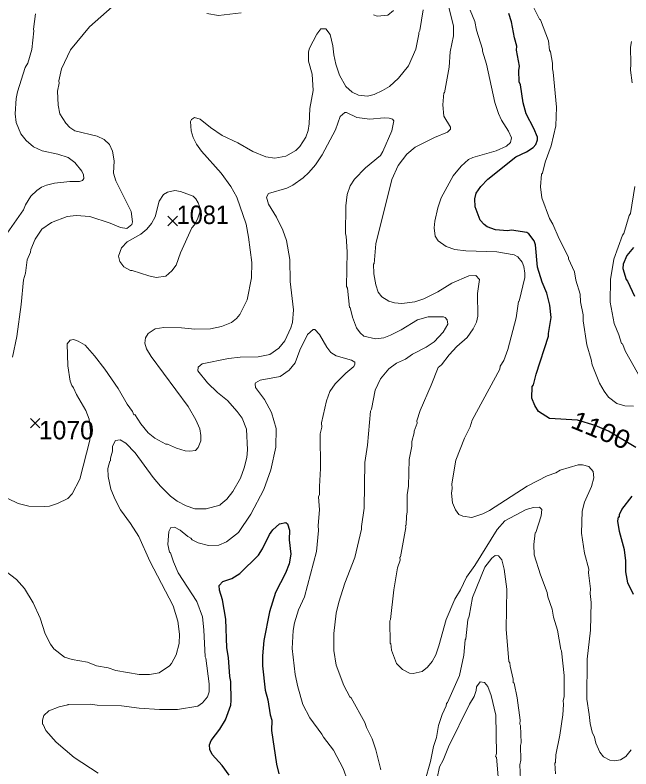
# Model space of a CAD drawing. Extents: x 265.7 to 292.1, y 7676.2 to 7704.2.
# Drawn here: x 285.928 to 288.593, y 7698.298 to 7701.561 of the extents above; entities that cross this region are included whole.
import ezdxf
from ezdxf.enums import TextEntityAlignment as Align

# ---------------------------------------------------------------- set-up
doc = ezdxf.new("R2010")
doc.units = 0
doc.header["$LTSCALE"] = 0.032
for name, color, linetype, lineweight in [('1', 7, 'Continuous', 25), ('2', 7, 'Continuous', 13), ('21', 7, 'Continuous', 25)]:
    doc.layers.add(name, color=color, linetype=linetype, lineweight=lineweight)
doc.layers.add('61', color=7, linetype='Continuous')

msp = doc.modelspace()

# ---------------------------------------------------------------- linework, layer by layer
at = {"layer": '1'}
for points in [[(288.6148, 7699.6898), (288.4962, 7699.76), (288.4378, 7699.7845), (288.3624, 7699.8071), (288.2413, 7699.8143), (288.1934, 7699.8446), (288.1767, 7699.871), (288.1639, 7699.9029), (288.1663, 7699.9539), (288.1711, 7699.9603), (288.1831, 7700.0066), (288.2365, 7700.1718), (288.2357, 7700.1822), (288.2477, 7700.2524), (288.2429, 7700.3051), (288.2294, 7700.3577), (288.2086, 7700.4056), (288.1887, 7700.4694), (288.1799, 7700.5668), (288.1751, 7700.5843), (288.152, 7700.6147), (288.1432, 7700.6202), (288.077, 7700.6306), (288.0594, 7700.6274), (288.0067, 7700.6314), (287.9716, 7700.645), (287.9573, 7700.6553), (287.9405, 7700.6737), (287.919, 7700.7312), (287.9174, 7700.7663), (287.9237, 7700.7902), (287.9437, 7700.8189), (287.9732, 7700.8508), (288.0945, 7700.9482), (288.1408, 7700.9689), (288.1703, 7700.9873), (288.1823, 7701.0009), (288.1887, 7701.0216), (288.1887, 7701.0328), (288.1735, 7701.0695), (288.14, 7701.1333), (288.1272, 7701.1812), (288.1153, 7701.2586), (288.1097, 7701.2722), (288.1081, 7701.3217), (288.1105, 7701.3392), (288.0985, 7701.4094), (288.0993, 7701.427), (288.0889, 7701.4621), (288.0761, 7701.5323), (288.0642, 7701.5674)], [(288.6044, 7700.5556), (288.5757, 7700.5205), (288.5589, 7700.4822), (288.5581, 7700.4646), (288.5725, 7700.416), (288.5789, 7700.4088), (288.6084, 7700.3441)], [(288.6044, 7699.0538), (288.5797, 7699.1033), (288.5717, 7699.1512), (288.5717, 7699.1991), (288.5653, 7699.247), (288.543, 7699.3252), (288.5366, 7699.3709), (288.5388, 7699.3896), (288.543, 7699.3898), (288.543, 7699.3994), (288.5533, 7699.4209), (288.598, 7699.4792)], [(286.8545, 7698.2718), (286.8241, 7698.3133), (286.7811, 7698.3612), (286.7707, 7698.382), (286.7691, 7698.4027), (286.7771, 7698.4211), (286.8146, 7698.4697), (286.8385, 7698.5112), (286.8609, 7698.5735), (286.8632, 7698.5942), (286.8617, 7698.6772), (286.8577, 7698.698), (286.8521, 7698.7809), (286.8449, 7698.8224), (286.8393, 7698.9469), (286.8249, 7699.0299), (286.8122, 7699.0714), (286.8106, 7699.0921), (286.8266, 7699.1097), (286.8657, 7699.1225), (286.9008, 7699.144), (286.9813, 7699.223), (286.9989, 7699.2501), (287.0284, 7699.3124), (287.0436, 7699.3331), (287.0723, 7699.3587), (287.1003, 7699.365), (287.1066, 7699.3594), (287.1154, 7699.3315), (287.1138, 7699.29), (287.1218, 7699.2278), (287.1138, 7699.1863), (287.0978, 7699.1448), (287.0548, 7699.0618), (287.0284, 7698.9788), (287.0045, 7698.8544), (286.9989, 7698.7873), (286.9989, 7698.7442), (287.0101, 7698.6389), (287.022, 7698.5974), (287.0324, 7698.532), (287.0396, 7698.5096), (287.038, 7698.465), (287.0587, 7698.3181), (287.0699, 7698.2766)]]:
    msp.add_lwpolyline(points, dxfattribs=at)
at = {"layer": '2'}
for points in [[(285.9169, 7700.08), (285.9352, 7700.1694), (285.9536, 7700.3082), (285.964, 7700.4152), (285.9727, 7700.4439), (285.9799, 7700.5013), (285.9943, 7700.5349), (285.9959, 7700.546), (286.015, 7700.5907), (286.0437, 7700.6346), (286.0852, 7700.6633), (286.1539, 7700.6897), (286.1922, 7700.6937), (286.2512, 7700.6897), (286.339, 7700.6609), (286.3837, 7700.641), (286.4116, 7700.637), (286.4332, 7700.6553), (286.4363, 7700.6657), (286.4308, 7700.7104), (286.3637, 7700.8429), (286.3542, 7700.8764), (286.3565, 7700.9307), (286.3494, 7700.9721), (286.3358, 7701.0009), (286.3135, 7701.0224), (286.2831, 7701.0376), (286.1858, 7701.0607), (286.165, 7701.0751), (286.1475, 7701.0934), (286.1219, 7701.1333), (286.114, 7701.1716), (286.1116, 7701.2323), (286.118, 7701.2658), (286.1172, 7701.277), (286.1283, 7701.3288), (286.1674, 7701.411), (286.2496, 7701.5108), (286.3486, 7701.5969)], [(287.8312, 7699.0331), (287.7929, 7698.9453), (287.7618, 7698.8304), (287.7482, 7698.7921), (287.733, 7698.7634), (287.7123, 7698.7386), (287.6899, 7698.7203), (287.6508, 7698.7107), (287.6349, 7698.7123), (287.6046, 7698.7283), (287.5782, 7698.7538), (287.5567, 7698.8129), (287.5543, 7698.8408), (287.5511, 7698.8416), (287.5495, 7698.9389), (287.5527, 7698.9445), (287.5671, 7699.073), (287.583, 7699.1688), (287.5942, 7699.2023), (287.5934, 7699.215), (287.5966, 7699.2166), (287.6189, 7699.3435), (287.6173, 7699.3515), (287.6197, 7699.3531), (287.6213, 7699.3922), (287.6253, 7699.4113), (287.6253, 7699.4847), (287.6301, 7699.5215), (287.6341, 7699.638), (287.6453, 7699.6954), (287.6453, 7699.7154), (287.6556, 7699.7529), (287.6548, 7699.7608), (287.6684, 7699.7951), (287.6668, 7699.8047), (287.6804, 7699.8502), (287.729, 7699.9587), (287.7594, 7700.0353), (287.7729, 7700.0473), (287.8064, 7700.0904), (287.84, 7700.1263), (287.8839, 7700.1654), (287.911, 7700.2029), (287.9253, 7700.2316), (287.9309, 7700.2572), (287.9285, 7700.3561), (287.9381, 7700.4168), (287.9221, 7700.4335), (287.8918, 7700.4319), (287.8184, 7700.4008), (287.7578, 7700.3625), (287.6971, 7700.3322), (287.6572, 7700.3202), (287.6014, 7700.313), (287.5695, 7700.3162), (287.5455, 7700.3226), (287.5144, 7700.341), (287.4992, 7700.3617), (287.4889, 7700.3928), (287.4809, 7700.4407), (287.4793, 7700.4846), (287.4817, 7700.4846), (287.4889, 7700.5716), (287.5583, 7700.8493), (287.5862, 7700.9099), (287.6237, 7700.9594), (287.6596, 7700.9889), (287.7434, 7701.0312), (287.7993, 7701.0543), (287.812, 7701.0671), (287.812, 7701.0759), (287.7841, 7701.1238), (287.7793, 7701.1732), (287.7841, 7701.2243), (287.7865, 7701.2251), (287.8064, 7701.336), (287.8104, 7701.4014), (287.8248, 7701.4717), (287.8248, 7701.514), (287.8009, 7701.6105)], [(286.0158, 7701.5658), (286.007, 7701.5004), (286.0086, 7701.4924), (286.0007, 7701.4126), (285.9831, 7701.3536), (285.9719, 7701.3344), (285.9384, 7701.2291), (285.9328, 7701.2004), (285.928, 7701.1333), (285.932, 7701.0966), (285.9528, 7701.0472), (285.9759, 7701.0184), (286.007, 7700.9913), (286.0454, 7700.9737), (286.1124, 7700.9586), (286.1571, 7700.9442), (286.1858, 7700.9227), (286.2161, 7700.8852), (286.2241, 7700.87), (286.2257, 7700.8532), (286.2193, 7700.8453), (286.2065, 7700.8405), (286.165, 7700.8405), (286.098, 7700.8341), (286.0645, 7700.8253), (286.0422, 7700.8157), (286.0214, 7700.8022), (285.9959, 7700.7774), (285.9727, 7700.7391), (285.964, 7700.7184), (285.8419, 7700.5452)], [(286.9056, 7701.5706), (286.8082, 7701.5594), (286.7571, 7701.5674)], [(287.5655, 7701.581), (287.5407, 7701.561), (287.4952, 7701.5562), (287.4785, 7701.5626)], [(287.6939, 7701.5834), (287.6796, 7701.494), (287.6748, 7701.486), (287.6756, 7701.4781), (287.662, 7701.4142), (287.6301, 7701.3408), (287.587, 7701.2873)], [(288.0714, 7701.0096), (288.0762, 7701.0296), (288.0626, 7701.0583), (288.0331, 7701.1062), (288.0195, 7701.1349), (288.0035, 7701.1828), (287.9676, 7701.3488), (287.9501, 7701.4054), (287.9509, 7701.4142), (287.9253, 7701.4956), (287.9174, 7701.5339), (287.8974, 7701.5818)], [(288.3554, 7700.4136), (288.3491, 7700.4503), (288.3235, 7700.5053), (288.3235, 7700.5125), (288.282, 7700.5923), (288.2549, 7700.6562), (288.2405, 7700.6801), (288.2078, 7700.7695), (288.2022, 7700.8173), (288.2062, 7700.8724), (288.2102, 7700.8764), (288.2222, 7700.9243), (288.2485, 7700.9945), (288.2677, 7701.0823), (288.2709, 7701.1621), (288.2573, 7701.3137), (288.2533, 7701.3288), (288.2533, 7701.3536), (288.2453, 7701.4014), (288.2413, 7701.4094), (288.2365, 7701.4493), (288.2014, 7701.5411), (288.1974, 7701.5435), (288.1727, 7701.593)], [(287.3867, 7701.2267), (287.3588, 7701.2522), (287.3317, 7701.3009), (287.3157, 7701.3488), (287.3069, 7701.3887), (287.3029, 7701.4286), (287.2918, 7701.4765), (287.2734, 7701.502), (287.2511, 7701.5012), (287.2335, 7701.4789), (287.2016, 7701.4174), (287.1976, 7701.4014), (287.1984, 7701.3616), (287.2136, 7701.3057), (287.2176, 7701.2339), (287.2032, 7701.1573), (287.2008, 7701.0902), (287.196, 7701.0615), (287.1864, 7701.0328), (287.1601, 7700.9929), (287.1433, 7700.9753), (287.1003, 7700.9498), (287.0524, 7700.9418), (287.0125, 7700.9474), (286.9566, 7700.9705), (286.8912, 7701.0088), (286.8242, 7701.04), (286.7731, 7701.0743), (286.7284, 7701.1102), (286.7037, 7701.1174), (286.6917, 7701.1094), (286.6869, 7701.1006), (286.6901, 7701.0599), (286.6989, 7701.0312), (286.7124, 7701.0025), (286.734, 7700.9721), (286.8194, 7700.8772), (286.8609, 7700.8189), (286.888, 7700.7735), (286.9279, 7700.6562), (286.9383, 7700.6003), (286.9526, 7700.4902), (286.951, 7700.4231), (286.9327, 7700.329), (286.9, 7700.2644), (286.8856, 7700.2476), (286.8641, 7700.23), (286.821, 7700.2133), (286.7731, 7700.2037), (286.7061, 7700.2021), (286.6486, 7700.2069), (286.572, 7700.2085), (286.5337, 7700.2029), (286.5034, 7700.183), (286.4922, 7700.1646), (286.4898, 7700.1407), (286.497, 7700.1167), (286.5161, 7700.0832), (286.6773, 7699.8662), (286.7108, 7699.8087), (286.7268, 7699.7704), (286.7316, 7699.7417), (286.7316, 7699.7185), (286.7196, 7699.689), (286.7093, 7699.677), (286.6837, 7699.6731), (286.6646, 7699.6747), (286.6263, 7699.6858), (286.588, 7699.7034), (286.5808, 7699.7034), (286.5329, 7699.7305), (286.5042, 7699.7529), (286.4715, 7699.7912), (286.4459, 7699.8318), (286.4411, 7699.831), (286.4355, 7699.8446), (286.4124, 7699.8773), (286.3741, 7699.9444), (286.3166, 7700.029), (286.272, 7700.0864), (286.2305, 7700.1327), (286.2002, 7700.1502), (286.181, 7700.1566), (286.1658, 7700.1542), (286.1539, 7700.1375), (286.1555, 7700.0433), (286.1666, 7699.9763), (286.173, 7699.9579), (286.181, 7699.9476), (286.1938, 7699.9188), (286.2337, 7699.8502), (286.248, 7699.8119), (286.2547, 7699.7614), (286.2519, 7699.7207), (286.2086, 7699.5526)], [(288.5956, 7701.4461), (288.5916, 7701.4222), (288.5932, 7701.3504), (288.5908, 7701.3232), (288.598, 7701.2674)], [(287.587, 7701.2873), (287.5487, 7701.2522), (287.5184, 7701.2339), (287.4817, 7701.2171), (287.453, 7701.2107), (287.4147, 7701.2147), (287.3867, 7701.2267)], [(286.3406, 7699.6427), (286.3494, 7699.6731), (286.3494, 7699.6954), (286.3621, 7699.7201), (286.3821, 7699.7233), (286.4076, 7699.7082), (286.4475, 7699.6667), (286.5257, 7699.559), (286.5576, 7699.5215), (286.6007, 7699.4784), (286.6295, 7699.4576), (286.6678, 7699.4369), (286.7061, 7699.4241), (286.7555, 7699.4241), (286.8146, 7699.4393), (286.8178, 7699.4448), (286.8449, 7699.4656), (286.8704, 7699.4983), (286.9039, 7699.5566), (286.9199, 7699.6012), (286.9303, 7699.6459), (286.9343, 7699.6794), (286.9287, 7699.7688), (286.9103, 7699.8167), (286.8896, 7699.8454), (286.8465, 7699.8925), (286.8034, 7699.9276), (286.7603, 7699.9691), (286.7188, 7700.021), (286.7196, 7700.0369), (286.7372, 7700.0513), (286.8513, 7700.0752), (286.9024, 7700.0808), (286.9806, 7700.0816), (287.0308, 7700.092), (287.0699, 7700.1199), (287.0955, 7700.1518), (287.1218, 7700.2077), (287.1282, 7700.23), (287.133, 7700.2859), (287.1186, 7700.4072), (287.117, 7700.5029), (287.1018, 7700.5859), (287.0867, 7700.6306), (287.0588, 7700.6865), (287.0252, 7700.7423), (287.0157, 7700.7734), (287.0244, 7700.7886), (287.1034, 7700.8118), (287.1298, 7700.8253), (287.1745, 7700.8572), (287.1992, 7700.8796), (287.2279, 7700.9123), (287.2574, 7700.9562), (287.3141, 7701.0647), (287.3348, 7701.1222), (287.3548, 7701.1397), (287.362, 7701.1389), (287.4067, 7701.1182), (287.4625, 7701.1102), (287.5248, 7701.1158), (287.5471, 7701.115), (287.5615, 7701.1102), (287.5671, 7701.103), (287.5583, 7701.0599), (287.5192, 7700.9706), (287.5088, 7700.9538), (287.445, 7700.9003), (287.3963, 7700.8509), (287.3779, 7700.8221), (287.3644, 7700.7838), (287.3588, 7700.7359), (287.358, 7700.6147), (287.3612, 7700.6035), (287.3644, 7700.5365), (287.3628, 7700.3864), (287.366, 7700.3785), (287.3755, 7700.2947), (287.3779, 7700.2947), (287.3875, 7700.254), (287.4051, 7700.2077), (287.4218, 7700.1854), (287.4378, 7700.1718), (287.4881, 7700.1598), (287.5232, 7700.1646), (287.5519, 7700.175), (287.5982, 7700.1981), (287.67, 7700.242), (287.7163, 7700.2548), (287.7817, 7700.2548), (287.7889, 7700.2524), (287.7985, 7700.242), (287.8001, 7700.2229), (287.7809, 7700.1885), (287.741, 7700.147)], [(287.8232, 7700.8652), (287.8583, 7700.9067), (287.8902, 7700.9354), (287.9094, 7700.945), (288.0099, 7700.9729), (288.0546, 7700.9937), (288.0714, 7701.0096)], [(288.594, 7698.3804), (288.5709, 7698.3524), (288.5478, 7698.3373), (288.5206, 7698.3325), (288.5015, 7698.3365), (288.4743, 7698.35), (288.4584, 7698.3708), (288.4408, 7698.4091), (288.436, 7698.4354), (288.4257, 7698.457), (288.4161, 7698.4953), (288.4129, 7698.5336), (288.4017, 7698.6006), (288.4033, 7698.773), (288.4185, 7698.899), (288.4217, 7699.0187), (288.4161, 7699.057), (288.4185, 7699.0778), (288.4097, 7699.1464), (288.4105, 7699.1632), (288.3922, 7699.2326), (288.3786, 7699.3188), (288.3826, 7699.4145), (288.3929, 7699.4528), (288.4225, 7699.5199), (288.432, 7699.5582), (288.4297, 7699.5861), (288.4105, 7699.6076), (288.3834, 7699.614), (288.3642, 7699.614), (288.2876, 7699.5909), (288.2685, 7699.5797), (288.2302, 7699.5669), (288.144, 7699.5214), (287.9812, 7699.4161), (287.9525, 7699.4025), (287.9046, 7699.3858), (287.8663, 7699.3922), (287.8479, 7699.3994), (287.8344, 7699.4193), (287.8216, 7699.4504), (287.8168, 7699.4911), (287.82, 7699.5119), (287.8184, 7699.5326), (287.836, 7699.6348), (287.8727, 7699.7305), (287.8974, 7699.7784), (287.9054, 7699.8071), (288.0251, 7700.0281), (288.0275, 7700.0417), (288.0434, 7700.0657), (288.061, 7700.1135), (288.0969, 7700.2508), (288.1065, 7700.3218), (288.1097, 7700.3234), (288.1336, 7700.4247), (288.1344, 7700.4439), (288.1296, 7700.4726), (288.1224, 7700.4918), (288.1041, 7700.5149), (288.0873, 7700.5229), (288.0131, 7700.5357), (287.8791, 7700.5404), (287.8312, 7700.5468), (287.7929, 7700.5596), (287.7586, 7700.5835), (287.7466, 7700.6043), (287.741, 7700.6402), (287.7442, 7700.6689), (287.7578, 7700.7264), (287.7721, 7700.7695), (287.8232, 7700.8652)], [(288.61, 7700.8189), (288.5916, 7700.7024), (288.5853, 7700.6937), (288.5621, 7700.6163), (288.5565, 7700.6083), (288.519, 7700.5045), (288.5047, 7700.4168), (288.5031, 7700.3186), (288.5206, 7700.2268), (288.5414, 7700.1774), (288.5525, 7700.1391), (288.5565, 7700.1375), (288.5701, 7700.1056), (288.6395, 7699.9827)], [(288.4209, 7700.0704), (288.4025, 7700.1343), (288.3858, 7700.238), (288.3858, 7700.2636), (288.3746, 7700.3194), (288.373, 7700.3529), (288.3554, 7700.4136)], [(287.3668, 7698.2479), (287.3476, 7698.3006), (287.3061, 7698.3788), (287.2622, 7698.4354), (287.2551, 7698.449), (287.2032, 7698.5192), (287.1737, 7698.5767), (287.1513, 7698.6533), (287.1394, 7698.7075), (287.1274, 7698.8192), (287.1314, 7698.8974), (287.1378, 7698.931), (287.1545, 7698.9868), (287.18, 7699.0427), (287.2319, 7699.239), (287.2407, 7699.3299), (287.2391, 7699.3523), (287.2447, 7699.4193), (287.2415, 7699.4752), (287.2455, 7699.4863), (287.2447, 7699.5199), (287.2495, 7699.5981), (287.2487, 7699.7481), (287.2559, 7699.7768), (287.2543, 7699.796), (287.2758, 7699.8917), (287.2902, 7699.9316), (287.3125, 7699.9643), (287.3588, 7700.0106), (287.3939, 7700.0393), (287.3987, 7700.0497), (287.3987, 7700.0585), (287.3835, 7700.068), (287.3173, 7700.0864), (287.2942, 7700.1008), (287.2766, 7700.1231), (287.2455, 7700.179), (287.2255, 7700.1997), (287.2176, 7700.1997), (287.1928, 7700.1782), (287.1609, 7700.1103), (287.1401, 7700.0561), (287.1146, 7700.0242), (287.0747, 7699.9962), (286.9885, 7699.9811), (286.9686, 7699.9699), (286.9662, 7699.9651), (286.9678, 7699.9492), (287.0077, 7699.8965), (287.038, 7699.8406), (287.058, 7699.772), (287.0564, 7699.6906), (287.034, 7699.5933), (287.0037, 7699.5071), (286.9478, 7699.4002), (286.8944, 7699.322), (286.8433, 7699.2805)], [(287.741, 7700.147), (287.7075, 7700.1239), (287.6477, 7700.0928), (287.6173, 7700.072), (287.579, 7700.0545), (287.5455, 7700.0297), (287.5088, 7699.9859)], [(288.6036, 7699.8686), (288.5661, 7699.8694), (288.5318, 7699.8805), (288.4967, 7699.9077), (288.4767, 7699.9332), (288.4568, 7699.9675), (288.4249, 7700.0465), (288.4209, 7700.0704)], [(287.5088, 7699.9859), (287.4857, 7699.938), (287.4705, 7699.855), (287.4665, 7699.847), (287.453, 7699.7002), (287.4418, 7699.6252), (287.4386, 7699.4273), (287.4266, 7699.3475), (287.4274, 7699.3355), (287.3979, 7699.2134), (287.3556, 7699.1017), (287.3293, 7699.0203), (287.3173, 7698.9725), (287.3069, 7698.8847), (287.3077, 7698.8113), (287.3173, 7698.7474), (287.35, 7698.6597), (287.3771, 7698.6102), (287.3827, 7698.6054), (287.4418, 7698.4993), (287.449, 7698.4777), (287.4729, 7698.4282), (287.4889, 7698.3804), (287.5104, 7698.2942)], [(286.3605, 7699.464), (286.3422, 7699.5087), (286.3302, 7699.5645), (286.3294, 7699.5981), (286.3374, 7699.6308), (286.3406, 7699.6316), (286.3406, 7699.6427)], [(286.2086, 7699.5526), (286.1742, 7699.489), (286.1562, 7699.4691), (286.1108, 7699.4464), (286.0773, 7699.4361), (286.0549, 7699.4337), (285.9879, 7699.4353)], [(285.8666, 7699.1703), (285.9336, 7699.1185), (285.9687, 7699.0794), (286.0062, 7699.0171), (286.0358, 7698.9501), (286.0581, 7698.8831), (286.0805, 7698.8384), (286.0956, 7698.8176), (286.1411, 7698.7825), (286.1746, 7698.7722), (286.2416, 7698.7602), (286.2807, 7698.745), (286.331, 7698.7362), (286.3645, 7698.7243), (286.4651, 7698.7067), (286.5098, 7698.7067), (286.5513, 7698.7147), (286.5959, 7698.745), (286.6047, 7698.7546), (286.6247, 7698.7921), (286.6374, 7698.8408), (286.639, 7698.8815), (286.6326, 7698.9373), (286.6119, 7699.0044), (286.5114, 7699.1975), (286.4635, 7699.3044), (286.4276, 7699.3603), (286.3837, 7699.4193), (286.3605, 7699.464)], [(285.9879, 7699.4353), (285.9408, 7699.4464), (285.8969, 7699.468)], [(288.1392, 7699.4217), (288.0474, 7699.3714), (288.0147, 7699.3347), (287.9174, 7699.1783), (287.8815, 7699.1281), (287.8551, 7699.073), (287.8312, 7699.0331)], [(288.2661, 7698.2766), (288.2637, 7698.3237), (288.2661, 7698.3261), (288.2677, 7698.3596), (288.2852, 7698.4442), (288.2988, 7698.532), (288.302, 7698.5767), (288.3004, 7698.5942), (288.3044, 7698.6102), (288.3044, 7698.7027), (288.2932, 7698.8097), (288.2892, 7698.8145), (288.2756, 7698.899), (288.2581, 7698.9549), (288.2517, 7698.99), (288.2334, 7699.0427), (288.2302, 7699.0618), (288.2014, 7699.1384), (288.1751, 7699.2246), (288.1735, 7699.2693), (288.1783, 7699.3204), (288.1815, 7699.322), (288.2046, 7699.3938), (288.2078, 7699.4209), (288.1975, 7699.4313), (288.1711, 7699.4297), (288.1392, 7699.4217)], [(286.6757, 7699.3036), (286.6422, 7699.3323), (286.6183, 7699.3443), (286.6023, 7699.3435), (286.5927, 7699.3252), (286.5896, 7699.2693), (286.5959, 7699.2366), (286.6007, 7699.2334), (286.6135, 7699.1943), (286.6342, 7699.1464), (286.714, 7699.0235), (286.7396, 7698.9565), (286.7452, 7698.9006), (286.7499, 7698.7833), (286.7539, 7698.7778), (286.7683, 7698.666), (286.7683, 7698.6325), (286.7611, 7698.6102), (286.7396, 7698.5838), (286.7188, 7698.5703), (286.6311, 7698.5559), (286.5529, 7698.5551), (286.4651, 7698.5615), (286.3885, 7698.5711), (286.2831, 7698.5735), (286.2528, 7698.579), (286.1571, 7698.5775), (286.1563, 7698.5751), (286.1188, 7698.5663), (286.0741, 7698.5495), (286.0525, 7698.5296), (286.0469, 7698.5096), (286.0469, 7698.4921), (286.0501, 7698.4905), (286.0613, 7698.465), (286.1052, 7698.4139), (286.1842, 7698.3476), (286.2879, 7698.2798)], [(286.8433, 7699.2805), (286.8098, 7699.2661), (286.7651, 7699.2653), (286.7204, 7699.2773), (286.6941, 7699.29), (286.6885, 7699.2972), (286.6757, 7699.3036)], [(287.7019, 7698.2431), (287.7258, 7698.3309), (287.7386, 7698.3947), (287.7522, 7698.4346), (287.761, 7698.4857), (287.7769, 7698.5336), (287.7937, 7698.5719), (287.7945, 7698.5815), (287.7993, 7698.5854), (287.8519, 7698.7027), (287.8703, 7698.7905), (287.8751, 7698.8575), (287.8783, 7698.8615), (287.8878, 7698.9437), (287.8934, 7698.9597), (287.9078, 7699.0395), (287.9613, 7699.1719), (287.9908, 7699.2102), (288.0059, 7699.2214), (288.0195, 7699.2198), (288.0339, 7699.2031), (288.0442, 7699.1624), (288.0562, 7699.0762), (288.0538, 7698.9038), (288.0642, 7698.7626), (288.069, 7698.757), (288.0698, 7698.7426), (288.0833, 7698.6868), (288.0841, 7698.6716), (288.0873, 7698.67), (288.1009, 7698.6054), (288.1145, 7698.5096), (288.1129, 7698.4921), (288.1153, 7698.4865), (288.1177, 7698.4107), (288.1153, 7698.3995), (288.1161, 7698.3357), (288.1129, 7698.3165), (288.1153, 7698.2527)], [(288.0187, 7698.2639), (288.0115, 7698.3492), (288.0067, 7698.35), (288.0107, 7698.3644), (288.0083, 7698.5304), (287.9884, 7698.6166), (287.974, 7698.6549), (287.9589, 7698.6724), (287.9413, 7698.6748), (287.9253, 7698.6533), (287.9237, 7698.6381), (287.9142, 7698.6118), (287.8942, 7698.5783), (287.8041, 7698.3931), (287.7801, 7698.3357), (287.7642, 7698.307), (287.745, 7698.2096)]]:
    msp.add_lwpolyline(points, dxfattribs=at)
msp.add_lwpolyline([(286.6929, 7700.6395), (286.7043, 7700.6531), (286.7179, 7700.6781), (286.727, 7700.7077), (286.7282, 7700.7258), (286.7202, 7700.7486), (286.71, 7700.7663), (286.6981, 7700.7774), (286.6438, 7700.7974), (286.6199, 7700.8014), (286.5872, 7700.7942), (286.5704, 7700.7838), (286.5513, 7700.7551), (286.5337, 7700.6881), (286.5177, 7700.6593), (286.4986, 7700.6338), (286.4715, 7700.6123), (286.4132, 7700.5795), (286.3885, 7700.5532), (286.3749, 7700.5173), (286.3805, 7700.4942), (286.398, 7700.471), (286.4268, 7700.4559), (286.4348, 7700.4559), (286.5066, 7700.4319), (286.5385, 7700.4247), (286.58, 7700.4311), (286.6063, 7700.4535), (286.6247, 7700.479), (286.6438, 7700.5325)], close=True, dxfattribs=at)
at = {"layer": '21'}
for p, q in [((286.5896, 7700.6903), (286.6308, 7700.6491)), ((286.6308, 7700.6903), (286.5896, 7700.6491)), ((285.994, 7699.8152), (286.0352, 7699.774)), ((286.0352, 7699.8152), (285.994, 7699.774))]:
    msp.add_line(p, q, dxfattribs=at)

# ---------------------------------------------------------------- texts
at = {"layer": '61', "width": 0.95}
msp.add_text('1081', height=0.08, dxfattribs=at).set_placement((286.7403, 7700.6566), align=Align.CENTER)
at = {"layer": '61', "width": 1.1}
msp.add_text('1100', height=0.08, rotation=337.7, dxfattribs=at).set_placement((288.4483, 7699.7276), align=Align.CENTER)
at = {"layer": '61'}
msp.add_text('1070', height=0.08, dxfattribs=at).set_placement((286.1498, 7699.7246), align=Align.CENTER)

doc.saveas('drawing.dxf')
